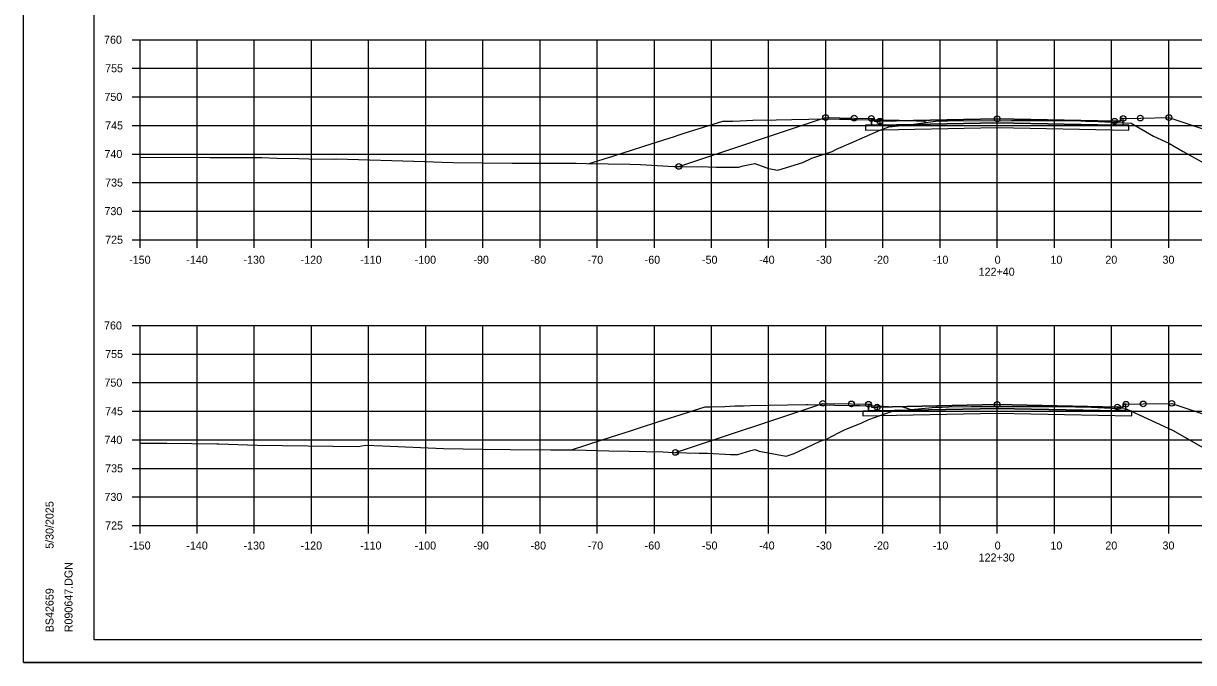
# Model space of a CAD drawing. Extents: x 1202951 to 1376887, y 378065 to 728038.
# Drawn here: x 1372926.7 to 1373131.5, y 381375.8 to 381487.6 of the extents above; entities that cross this region are included whole.
import ezdxf

# ---------------------------------------------------------------- set-up
doc = ezdxf.new("R2010")
doc.units = 0
for name, color, linetype in [('Default', 7, 'Continuous'), ('R_Alt Surface', 7, 'Continuous'), ('R_Axis', 7, 'Continuous'), ('R_Axis Annot', 7, 'Continuous'), ('R_Exist Surface', 7, 'Continuous'), ('R_Fin Surface', 7, 'Continuous'), ('R_Grid', 7, 'Continuous'), ('R_No Plot', 7, 'Continuous')]:
    doc.layers.add(name, color=color, linetype=linetype)

msp = doc.modelspace()

# ---------------------------------------------------------------- linework, layer by layer
at = {"layer": 'Default'}
for points in [[(1373075.1, 381470.98), (1373075.59, 381470.98), (1373075.6, 381470.48), (1373076.6, 381470.5), (1373076.6, 381469.83), (1373075.1, 381469.8)], [(1373119.17, 381470.98), (1373118.68, 381470.98), (1373118.67, 381470.48), (1373117.67, 381470.5), (1373117.67, 381469.83), (1373119.17, 381469.8)], [(1373074.61, 381420.97), (1373075.1, 381420.97), (1373075.11, 381420.47), (1373076.11, 381420.49), (1373076.11, 381419.83), (1373074.61, 381419.8)], [(1373119.66, 381420.97), (1373119.17, 381420.97), (1373119.16, 381420.47), (1373118.16, 381420.49), (1373118.16, 381419.83), (1373119.66, 381419.8)]]:
    msp.add_lwpolyline(points, close=True, dxfattribs=at)
at = {"layer": 'R_Alt Surface'}
for points in [[(1373097.13, 381470.24), (1373076.6, 381469.83), (1373075.1, 381469.8), (1373074.1, 381469.78), (1373074.1, 381468.95), (1373097.13, 381469.41), (1373120.17, 381468.95), (1373120.17, 381469.78), (1373119.17, 381469.8), (1373117.67, 381469.83)], [(1373076.6, 381470.5), (1373076.6, 381469.83), (1373097.13, 381470.24), (1373117.67, 381469.83), (1373117.67, 381470.5), (1373117.67, 381470.5), (1373097.13, 381470.91), (1373076.6, 381470.5)], [(1373076.11, 381420.49), (1373076.11, 381419.83), (1373097.13, 381420.25), (1373118.16, 381419.83), (1373118.16, 381420.49), (1373118.16, 381420.49), (1373097.13, 381420.91), (1373076.11, 381420.49)], [(1373097.13, 381420.25), (1373076.11, 381419.83), (1373074.61, 381419.8), (1373073.61, 381419.78), (1373073.61, 381418.94), (1373097.13, 381419.41), (1373120.66, 381418.94), (1373120.66, 381419.78), (1373119.66, 381419.8), (1373118.16, 381419.83)]]:
    msp.add_lwpolyline(points, close=True, dxfattribs=at)
for points in [[(1373075.1, 381470.98), (1373075.1, 381469.8), (1373076.6, 381469.83), (1373097.13, 381470.24), (1373117.67, 381469.83), (1373119.17, 381469.8), (1373119.17, 381470.98)], [(1373074.61, 381420.97), (1373074.61, 381419.8), (1373076.11, 381419.83), (1373097.13, 381420.25), (1373118.16, 381419.83), (1373119.66, 381419.8), (1373119.66, 381420.97)]]:
    msp.add_lwpolyline(points, dxfattribs=at)
at = {"layer": 'R_Axis'}
for p, q in [((1372945.73, 381484.76), (1372947.13, 381484.76)), ((1372947.13, 381449.76), (1372947.13, 381484.76)), ((1372945.73, 381479.76), (1372947.13, 381479.76)), ((1372945.73, 381474.76), (1372947.13, 381474.76)), ((1372945.73, 381469.76), (1372947.13, 381469.76)), ((1372945.73, 381464.76), (1372947.13, 381464.76)), ((1372945.73, 381459.76), (1372947.13, 381459.76)), ((1372945.73, 381454.76), (1372947.13, 381454.76)), ((1372945.73, 381449.76), (1372947.13, 381449.76)), ((1372947.13, 381449.76), (1373247.13, 381449.76)), ((1372947.13, 381448.36), (1372947.13, 381449.76)), ((1372957.13, 381448.36), (1372957.13, 381449.76)), ((1372967.13, 381448.36), (1372967.13, 381449.76)), ((1372977.13, 381448.36), (1372977.13, 381449.76)), ((1372987.13, 381448.36), (1372987.13, 381449.76)), ((1372997.13, 381448.36), (1372997.13, 381449.76)), ((1373007.13, 381448.36), (1373007.13, 381449.76)), ((1373017.13, 381448.36), (1373017.13, 381449.76)), ((1373027.13, 381448.36), (1373027.13, 381449.76)), ((1373037.13, 381448.36), (1373037.13, 381449.76)), ((1373047.13, 381448.36), (1373047.13, 381449.76)), ((1373057.13, 381448.36), (1373057.13, 381449.76)), ((1373067.13, 381448.36), (1373067.13, 381449.76)), ((1373077.13, 381448.36), (1373077.13, 381449.76)), ((1373087.13, 381448.36), (1373087.13, 381449.76)), ((1373097.13, 381448.36), (1373097.13, 381449.76)), ((1373107.13, 381448.36), (1373107.13, 381449.76)), ((1373117.13, 381448.36), (1373117.13, 381449.76)), ((1373127.13, 381448.36), (1373127.13, 381449.76)), ((1372945.73, 381434.76), (1372947.13, 381434.76)), ((1372947.13, 381399.76), (1372947.13, 381434.76)), ((1372945.73, 381429.76), (1372947.13, 381429.76)), ((1372945.73, 381424.76), (1372947.13, 381424.76)), ((1372945.73, 381419.76), (1372947.13, 381419.76)), ((1372945.73, 381414.76), (1372947.13, 381414.76)), ((1372945.73, 381409.76), (1372947.13, 381409.76)), ((1372945.73, 381404.76), (1372947.13, 381404.76)), ((1372945.73, 381399.76), (1372947.13, 381399.76)), ((1372947.13, 381399.76), (1373247.13, 381399.76)), ((1372947.13, 381398.36), (1372947.13, 381399.76)), ((1372957.13, 381398.36), (1372957.13, 381399.76)), ((1372967.13, 381398.36), (1372967.13, 381399.76)), ((1372977.13, 381398.36), (1372977.13, 381399.76)), ((1372987.13, 381398.36), (1372987.13, 381399.76)), ((1372997.13, 381398.36), (1372997.13, 381399.76)), ((1373007.13, 381398.36), (1373007.13, 381399.76)), ((1373017.13, 381398.36), (1373017.13, 381399.76)), ((1373027.13, 381398.36), (1373027.13, 381399.76)), ((1373037.13, 381398.36), (1373037.13, 381399.76)), ((1373047.13, 381398.36), (1373047.13, 381399.76)), ((1373057.13, 381398.36), (1373057.13, 381399.76)), ((1373067.13, 381398.36), (1373067.13, 381399.76)), ((1373077.13, 381398.36), (1373077.13, 381399.76)), ((1373087.13, 381398.36), (1373087.13, 381399.76)), ((1373097.13, 381398.36), (1373097.13, 381399.76)), ((1373107.13, 381398.36), (1373107.13, 381399.76)), ((1373117.13, 381398.36), (1373117.13, 381399.76)), ((1373127.13, 381398.36), (1373127.13, 381399.76))]:
    msp.add_line(p, q, dxfattribs=at)
at = {"layer": 'R_Exist Surface'}
for points in [[(1372947.13, 381464.19), (1372959.4, 381464.13), (1372965.15, 381464.15), (1372967.8, 381464.16), (1372968.45, 381464.14), (1372971.09, 381464.04), (1372974.92, 381463.96), (1372976.67, 381463.91), (1372981.16, 381463.85), (1372981.49, 381463.9), (1372996.95, 381463.45), (1373000, 381463.32), (1373001.98, 381463.27), (1373012.23, 381463.15), (1373014.33, 381463.14), (1373023.44, 381463.13), (1373025.23, 381463.09), (1373032.86, 381462.97), (1373034.72, 381462.92), (1373040.53, 381462.6), (1373042.05, 381462.57), (1373046.56, 381462.52), (1373047.93, 381462.45), (1373051.89, 381462.45), (1373052.66, 381462.68), (1373054.74, 381463.08), (1373057.13, 381462.22), (1373058.75, 381461.93), (1373063.12, 381463.28), (1373064.67, 381464.03), (1373068.23, 381465.2), (1373068.99, 381465.61), (1373071.95, 381466.88), (1373073, 381467.33), (1373076.75, 381469.01), (1373078.14, 381469.5), (1373082.08, 381469.91), (1373086.31, 381470.48), (1373088.36, 381470.59), (1373088.38, 381470.59), (1373088.47, 381470.59), (1373099.64, 381470.64), (1373102.29, 381470.63), (1373110.77, 381470.61), (1373110.86, 381470.61), (1373112.62, 381470.53), (1373113.68, 381470.48), (1373120.56, 381470.17), (1373124.5, 381467.86), (1373127.17, 381466.63), (1373129.69, 381465.19), (1373135.31, 381462.02)], [(1373025.7, 381463.08), (1373029.86, 381464.41), (1373031.69, 381464.99), (1373036.74, 381466.6), (1373040.64, 381467.84), (1373041.27, 381468.03), (1373042.37, 381468.39), (1373049.09, 381470.51), (1373049.4, 381470.51), (1373050.15, 381470.51), (1373050.78, 381470.53), (1373052.17, 381470.59), (1373054.37, 381470.67), (1373058.47, 381470.75), (1373061.18, 381470.8), (1373067.11, 381470.91), (1373069.5, 381470.86), (1373071.45, 381470.83), (1373072.37, 381470.81), (1373075.5, 381470.75), (1373077.22, 381470.72), (1373079.96, 381470.67), (1373081.66, 381470.6), (1373084.26, 381470.51), (1373084.39, 381470.47), (1373084.94, 381470.3)], [(1373041.42, 381462.58), (1373067.1, 381471.14), (1373072.1, 381471.04), (1373075.1, 381470.98), (1373075.59, 381470.98), (1373075.6, 381470.48), (1373076.6, 381470.5), (1373097.13, 381470.91), (1373117.67, 381470.5), (1373118.67, 381470.48), (1373118.68, 381470.98), (1373119.17, 381470.98), (1373122.17, 381471.04), (1373127.17, 381471.14), (1373151.2, 381463.13)], [(1372947.13, 381414.17), (1372951.81, 381414.15), (1372960.6, 381414.04), (1372960.8, 381414.03), (1372960.92, 381414.03), (1372967.65, 381413.84), (1372985.32, 381413.61), (1372986.6, 381413.8), (1372989.56, 381413.71), (1373000.21, 381413.26), (1373007.11, 381413.09), (1373011.91, 381413.03), (1373019.02, 381413), (1373023.24, 381412.99), (1373029.15, 381412.84), (1373032.66, 381412.79), (1373038.68, 381412.65), (1373040.56, 381412.54), (1373045, 381412.44), (1373046.46, 381412.43), (1373050.47, 381412.21), (1373051.76, 381412.21), (1373054.03, 381412.9), (1373054.71, 381413.03), (1373055.49, 381412.75), (1373060.2, 381411.9), (1373061.62, 381412.34), (1373066.12, 381414.49), (1373067.26, 381414.87), (1373069.47, 381416.06), (1373070.41, 381416.47), (1373073.45, 381417.75), (1373074.64, 381418.29), (1373078.61, 381419.68), (1373082.64, 381420.11), (1373086.4, 381420.44), (1373087.47, 381420.48), (1373088.64, 381420.55), (1373092.56, 381420.57), (1373099.88, 381420.61), (1373107.23, 381420.56), (1373110.8, 381420.55), (1373111.45, 381420.52), (1373112.42, 381420.5), (1373119.38, 381420.2), (1373119.68, 381420.19), (1373121.97, 381419.13), (1373127.79, 381416.45), (1373135.67, 381411.93)], [(1373022.63, 381412.99), (1373027.99, 381414.72), (1373030.72, 381415.6), (1373032.95, 381416.32), (1373034.52, 381416.83), (1373037.76, 381417.87), (1373042.92, 381419.53), (1373044, 381419.87), (1373046, 381420.51), (1373046.69, 381420.51), (1373047.04, 381420.51), (1373049.49, 381420.61), (1373051.2, 381420.67), (1373052.72, 381420.7), (1373053.94, 381420.73), (1373063.72, 381420.91), (1373063.95, 381420.91), (1373068.74, 381420.82), (1373071.61, 381420.76), (1373072.13, 381420.75), (1373073.09, 381420.73), (1373076.33, 381420.67), (1373078.09, 381420.6), (1373080.54, 381420.51), (1373081.47, 381420.22), (1373082.02, 381420.04)], [(1373040.82, 381412.54), (1373066.61, 381421.13), (1373071.61, 381421.03), (1373074.61, 381420.97), (1373075.1, 381420.97), (1373075.11, 381420.47), (1373076.11, 381420.49), (1373097.13, 381420.91), (1373118.16, 381420.49), (1373119.16, 381420.47), (1373119.17, 381420.97), (1373119.66, 381420.97), (1373122.66, 381421.03), (1373127.66, 381421.13), (1373152.3, 381412.92)]]:
    msp.add_lwpolyline(points, dxfattribs=at)
at = {"layer": 'R_Fin Surface'}
for points in [[(1373067.1, 381471.14), (1373072.1, 381471.04), (1373075.1, 381470.98), (1373075.59, 381470.98), (1373075.6, 381470.48), (1373076.6, 381470.5), (1373076.6, 381470.5), (1373097.13, 381470.91), (1373117.67, 381470.5), (1373117.67, 381470.5), (1373118.67, 381470.48), (1373118.68, 381470.98), (1373119.17, 381470.98), (1373122.17, 381471.04), (1373127.17, 381471.14)], [(1373066.61, 381421.13), (1373071.61, 381421.03), (1373074.61, 381420.97), (1373075.1, 381420.97), (1373075.11, 381420.47), (1373076.11, 381420.49), (1373076.11, 381420.49), (1373097.13, 381420.91), (1373118.16, 381420.49), (1373118.16, 381420.49), (1373119.16, 381420.47), (1373119.17, 381420.97), (1373119.66, 381420.97), (1373122.66, 381421.03), (1373127.66, 381421.13)]]:
    msp.add_lwpolyline(points, dxfattribs=at)
at = {"layer": 'R_Grid'}
for p, q in [((1372947.13, 381484.76), (1373247.13, 381484.76)), ((1372947.13, 381449.76), (1372947.13, 381484.76)), ((1372957.13, 381449.76), (1372957.13, 381484.76)), ((1372967.13, 381449.76), (1372967.13, 381484.76)), ((1372977.13, 381449.76), (1372977.13, 381484.76)), ((1372987.13, 381449.76), (1372987.13, 381484.76)), ((1372997.13, 381449.76), (1372997.13, 381484.76)), ((1373007.13, 381449.76), (1373007.13, 381484.76)), ((1373017.13, 381449.76), (1373017.13, 381484.76)), ((1373027.13, 381449.76), (1373027.13, 381484.76)), ((1373037.13, 381449.76), (1373037.13, 381484.76)), ((1373047.13, 381449.76), (1373047.13, 381484.76)), ((1373057.13, 381449.76), (1373057.13, 381484.76)), ((1373067.13, 381449.76), (1373067.13, 381484.76)), ((1373077.13, 381449.76), (1373077.13, 381484.76)), ((1373087.13, 381449.76), (1373087.13, 381484.76)), ((1373097.13, 381449.76), (1373097.13, 381484.76)), ((1373107.13, 381449.76), (1373107.13, 381484.76)), ((1373117.13, 381449.76), (1373117.13, 381484.76)), ((1373127.13, 381449.76), (1373127.13, 381484.76)), ((1372947.13, 381479.76), (1373247.13, 381479.76)), ((1372947.13, 381474.76), (1373247.13, 381474.76)), ((1372947.13, 381469.76), (1373247.13, 381469.76)), ((1372947.13, 381464.76), (1373247.13, 381464.76)), ((1372947.13, 381459.76), (1373247.13, 381459.76)), ((1372947.13, 381454.76), (1373247.13, 381454.76)), ((1372947.13, 381449.76), (1373247.13, 381449.76)), ((1372947.13, 381434.76), (1373247.13, 381434.76)), ((1372947.13, 381399.76), (1372947.13, 381434.76)), ((1372957.13, 381399.76), (1372957.13, 381434.76)), ((1372967.13, 381399.76), (1372967.13, 381434.76)), ((1372977.13, 381399.76), (1372977.13, 381434.76)), ((1372987.13, 381399.76), (1372987.13, 381434.76)), ((1372997.13, 381399.76), (1372997.13, 381434.76)), ((1373007.13, 381399.76), (1373007.13, 381434.76)), ((1373017.13, 381399.76), (1373017.13, 381434.76)), ((1373027.13, 381399.76), (1373027.13, 381434.76)), ((1373037.13, 381399.76), (1373037.13, 381434.76)), ((1373047.13, 381399.76), (1373047.13, 381434.76)), ((1373057.13, 381399.76), (1373057.13, 381434.76)), ((1373067.13, 381399.76), (1373067.13, 381434.76)), ((1373077.13, 381399.76), (1373077.13, 381434.76)), ((1373087.13, 381399.76), (1373087.13, 381434.76)), ((1373097.13, 381399.76), (1373097.13, 381434.76)), ((1373107.13, 381399.76), (1373107.13, 381434.76)), ((1373117.13, 381399.76), (1373117.13, 381434.76)), ((1373127.13, 381399.76), (1373127.13, 381434.76)), ((1372947.13, 381429.76), (1373247.13, 381429.76)), ((1372947.13, 381424.76), (1373247.13, 381424.76)), ((1372947.13, 381419.76), (1373247.13, 381419.76)), ((1372947.13, 381414.76), (1373247.13, 381414.76)), ((1372947.13, 381409.76), (1373247.13, 381409.76)), ((1372947.13, 381404.76), (1373247.13, 381404.76)), ((1372947.13, 381399.76), (1373247.13, 381399.76))]:
    msp.add_line(p, q, dxfattribs=at)
at = {"layer": 'R_No Plot'}
for p, q in [((1372939.13, 381379.76), (1372939.13, 381585.22)), ((1372939.13, 381379.76), (1372939.13, 381379.76)), ((1373255.31, 381379.76), (1372939.13, 381379.76)), ((1372926.73, 381375.78), (1373260.07, 381375.78))]:
    msp.add_line(p, q, dxfattribs=at)
for points in [[(1372926.73, 381589.11), (1373260.07, 381589.11), (1373260.07, 381375.77), (1372926.73, 381375.77)], [(1373173.05, 381585.22), (1373192.67, 381585.22), (1373192.67, 381575.34), (1373208.79, 381575.34), (1373231.99, 381575.34), (1373231.99, 381551), (1373255.31, 381551), (1373255.31, 381379.76), (1372939.13, 381379.76), (1372939.13, 381585.22)]]:
    msp.add_lwpolyline(points, close=True, dxfattribs=at)
for centre in [(1373067.1, 381471.14), (1373127.17, 381471.14), (1373072.1, 381471.04), (1373075.1, 381470.98), (1373076.6, 381470.5), (1373097.13, 381470.91), (1373117.67, 381470.5), (1373119.17, 381470.98), (1373122.17, 381471.04), (1373041.42, 381462.58), (1373066.61, 381421.13), (1373071.61, 381421.03), (1373074.61, 381420.97), (1373076.11, 381420.49), (1373097.13, 381420.91), (1373118.16, 381420.49), (1373119.66, 381420.97), (1373122.66, 381421.03), (1373127.66, 381421.13), (1373040.82, 381412.54)]:
    msp.add_circle(centre, 0.5, dxfattribs=at)

# ---------------------------------------------------------------- texts
at = {"layer": 'R_Axis Annot'}
for s, p in [('760', (1372940.84, 381484.06)), ('755', (1372941.03, 381479.06)), ('750', (1372940.91, 381474.06)), ('745', (1372941.03, 381469.06)), ('740', (1372940.91, 381464.06)), ('735', (1372941.03, 381459.06)), ('730', (1372940.91, 381454.06)), ('725', (1372941.03, 381449.06)), ('-150', (1372945.24, 381445.56)), ('-140', (1372955.24, 381445.56)), ('-130', (1372965.24, 381445.56)), ('-120', (1372975.24, 381445.56)), ('-110', (1372985.64, 381445.56)), ('-100', (1372995.19, 381445.56)), ('-90', (1373005.47, 381445.56)), ('-80', (1373015.47, 381445.56)), ('-70', (1373025.47, 381445.56)), ('-60', (1373035.44, 381445.56)), ('-50', (1373045.47, 381445.56)), ('-40', (1373055.47, 381445.56)), ('-30', (1373065.47, 381445.56)), ('-20', (1373075.47, 381445.56)), ('-10', (1373085.87, 381445.56)), ('0', (1373096.68, 381445.56)), ('10', (1373106.44, 381445.56)), ('20', (1373116.05, 381445.56)), ('30', (1373126.05, 381445.56)), ('122+40', (1373093.88, 381443.46)), ('760', (1372940.84, 381434.06)), ('755', (1372941.03, 381429.06)), ('750', (1372940.91, 381424.06)), ('745', (1372941.03, 381419.06)), ('740', (1372940.91, 381414.06)), ('735', (1372941.03, 381409.06)), ('730', (1372940.91, 381404.06)), ('725', (1372941.03, 381399.06)), ('-150', (1372945.24, 381395.56)), ('-140', (1372955.24, 381395.56)), ('-130', (1372965.24, 381395.56)), ('-120', (1372975.24, 381395.56)), ('-110', (1372985.64, 381395.56)), ('-100', (1372995.19, 381395.56)), ('-90', (1373005.47, 381395.56)), ('-80', (1373015.47, 381395.56)), ('-70', (1373025.47, 381395.56)), ('-60', (1373035.44, 381395.56)), ('-50', (1373045.47, 381395.56)), ('-40', (1373055.47, 381395.56)), ('-30', (1373065.47, 381395.56)), ('-20', (1373075.47, 381395.56)), ('-10', (1373085.87, 381395.56)), ('0', (1373096.68, 381395.56)), ('10', (1373106.44, 381395.56)), ('20', (1373116.05, 381395.56)), ('30', (1373126.05, 381395.56)), ('122+30', (1373093.88, 381393.46))]:
    msp.add_text(s, height=1.4, dxfattribs=at).set_placement(p)
at = {"layer": 'R_No Plot'}
for s, p in [('5/30/2025', (1372932, 381395.68)), ('R090647.DGN', (1372935.32, 381381.08)), ('BS42659', (1372932, 381381.08))]:
    msp.add_text(s, height=1.4, rotation=90, dxfattribs=at).set_placement(p)

doc.saveas('drawing.dxf')
